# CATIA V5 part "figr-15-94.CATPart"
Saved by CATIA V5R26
Part number: Part1
Bounding box of the stored display mesh (mm): x -40 to 40, y -60 to 60, z -4 to 2
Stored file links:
  D:\_Deepak\CATIA\CATIA V5 2015 Parts Files\Part files\Partfiles\c15_catia_v5_6r2015_prt\figr-15-94.CATPart
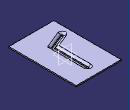
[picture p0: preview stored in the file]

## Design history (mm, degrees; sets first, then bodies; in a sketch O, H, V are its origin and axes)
SheetMetalParameters1: Thickness 2, BendRadius 4, KFactor 0.400515 {= log(min(100,max(20*SheetMetalParameters1.BendRadius,SheetMetalParameters1.Thickness)/SheetMetalParameters1.Thickness))/log(100)/2}, ReliefRadialLength 1, ReliefAxialLength 2, MinimumBendRadius 0
Body1 (main body)
  Sketch1 on xy-plane, origin (0, 0, 0), H (-1, 0, 0), V (0, -1, 0)
    line L1 (40, 60) -> (40, -60)
    line L2 (40, -60) -> (-40, -60)
    line L3 (-40, -60) -> (-40, 60)
    line L4 (-40, 60) -> (40, 60)
    length L4 = 80
    length L1 = 120
    vertical: L1 V, L3 V
    horizontal: L2 H, L4 H
    equidistance: L1 L3 O, L2 L4 O
  Wall1: Thickness 2, Profile Sketch1, OffsetValue 0
  Sketch2 on face of Wall1, origin (0, 0, 2), H (1, 0, 0), V (0, 1, 0)
    line L1 (0, 40.0798) -> (0, -21.0085)
    line L2 (0, -21.0085) -> (-27, -32)
    vertical: L1 V
  d_Stamp1: NewRoot_AttribNormalisation "No Standard", Stamp_FilletRadius 2, Stamp_IntersectFilletRadius 2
